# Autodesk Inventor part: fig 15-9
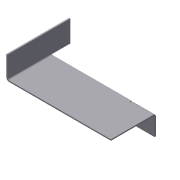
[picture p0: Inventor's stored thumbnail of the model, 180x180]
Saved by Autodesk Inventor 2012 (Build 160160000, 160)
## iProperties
Shininess: 77.0
Angle Display Precision: 2
Document Length Units: 11269
Document Angle Units: 11279
Document Time Units: 11290
Document Mass Units: 11283
Document Length Units Precision: 3
Document Angle Units Precision: 2
Created: 2002-04
Part Number: fig 15-9
Material: Aluminum-6061
Document SubType Name: Sheet Metal
Density: 1 g/cm^3
Sheet Metal Rule: Default
Density: 0.0
Volumn: 0.0
Area: 0.0
PropertySet Name: Model Information
Control State: 0
Master: False
Checked Out: False
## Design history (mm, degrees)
node "Face1"
  sketch "Sketch1"
    geometry: L1 (-49.559, 19.574)-(-49.559, -30.426); L2 (-49.559, -30.426)-(50.441, -30.426); L3 (50.441, -30.426)-(50.441, 19.574); L4 (50.441, 19.574)-(32.941, 19.574); L5 (32.941, 19.574)-(32.941, 4.574); L6 (32.941, 4.574)-(-32.059, 4.574); L7 (-32.059, 4.574)-(-32.059, 19.574); L8 (-32.059, 19.574)-(-49.559, 19.574)
    constraints: 16 end point, 6 parallel, 2 equal length, 1 perpendicular, 1 vertical
    dimensions: "d0" = 100 distance of L1.end L2.end; "d1" = 65 distance of L5.end L6.end; "d2" = 15 distance of L6.end L7.end; "d3" = 50 distance of L1.start L1.end
sketch "Sketch2"
  geometry: L1 (100, 0)-(0, 0) reference; L2 (17.5, 50)-(17.5, 35) reference; L3 (82.5, 50)-(82.5, 0)
  constraints: 2 end point, 1 parallel, 1 point on line
sketch "Sketch3"
  geometry: L1 (81.369, -50)-(0, -50) reference; L2 (17.5, 0)-(17.5, -50)
  constraints: 2 end point, 1 perpendicular, 1 point on line
feature "Fold2" sketch "Sketch3" dims "d8" = 1 (= BendRadius), "d9" = 90 deg, "d10" = 1 (= BendRadius), "d14" = 1 (= BendReliefWidth), "d15" = 0.5 (= BendReliefDepth), "d16" = 2 (= MinimumRemnant), "SeamGap" = 0.01, "Thickness" = 1
sketch "Sketch4"
  geometry: L1 (17.5, 0)-(17.5, -50) reference; L2 (-63.869, -15)-(0, -15) reference; L3 (0, -15)-(17.5, -15)
  constraints: 2 end point, 1 collinear, 1 point on line
feature "Fold3" sketch "Sketch4" dims "d11" = 1 (= BendRadius), "d12" = 90 deg, "d13" = 1 (= BendRadius), "d17" = 1 (= BendReliefWidth), "d18" = 0.5 (= BendReliefDepth), "d19" = 2 (= MinimumRemnant), "SeamGap" = 0.01, "Thickness" = 1
body "Solid1"
face "Plate1" dims "Thickness" = 1
other parameters: "BendRadius" = 1 (= Thickness), "BendReliefWidth" = 1 (= Thickness), "BendReliefDepth" = 0.5 (= 0.5 x Thickness), "CornerReliefSize" = 4 (= 4 x Thickness), "MinimumRemnant" = 2 (= 2 x Thickness), "TransitionRadius" = 1 (= BendRadius), "d4" = 1 (= BendRadius), "JacobiRadiusSize" = 1 (= Thickness), "GapSize" = 1 (= Thickness)
